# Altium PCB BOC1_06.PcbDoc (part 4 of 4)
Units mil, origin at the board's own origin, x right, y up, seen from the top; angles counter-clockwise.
Board outline 7900 x 6500 mil, 2 copper layers (Top Layer, Bottom Layer); 312 components, 413 nets, 1710 pads, 368 vias.
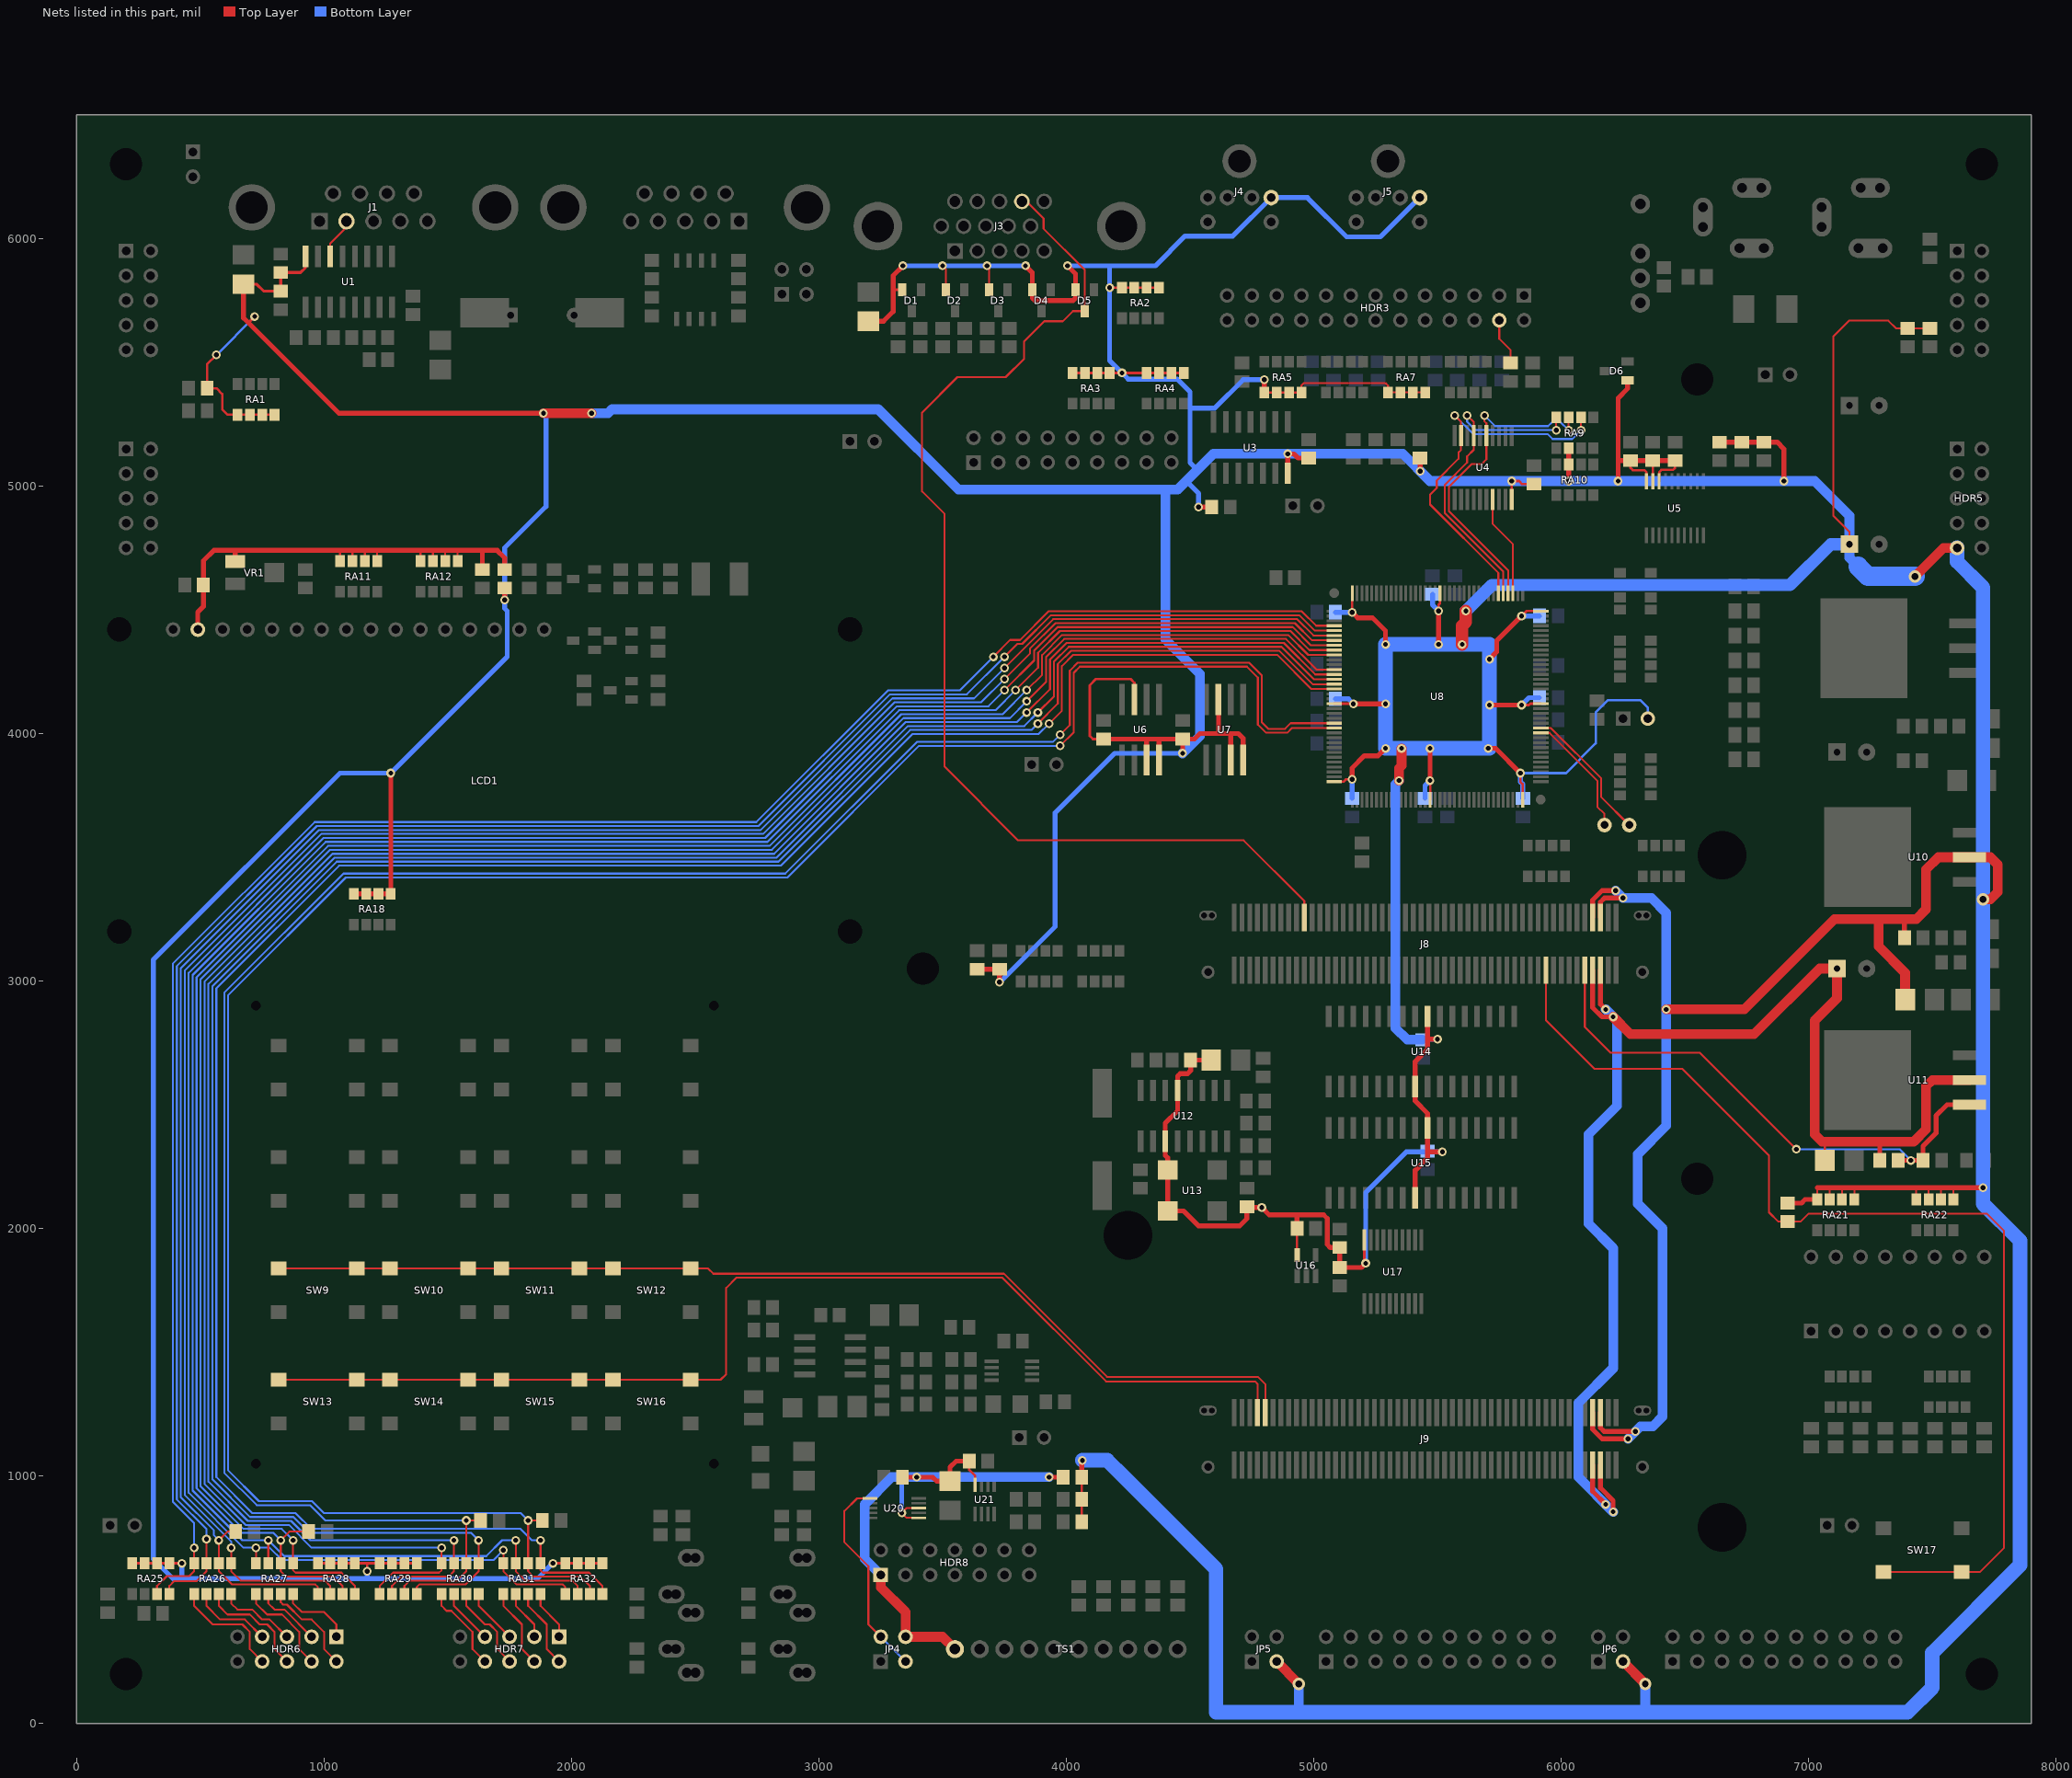
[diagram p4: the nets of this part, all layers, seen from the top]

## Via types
v1: diameter 35.43, hole 19.68, Top Layer to Bottom Layer, 194 vias
v2: diameter 35.43, hole 19.68, Top Layer to Bottom Layer, tented both sides, 169 vias
v3: diameter 50, hole 27.56, Top Layer to Bottom Layer, 5 vias

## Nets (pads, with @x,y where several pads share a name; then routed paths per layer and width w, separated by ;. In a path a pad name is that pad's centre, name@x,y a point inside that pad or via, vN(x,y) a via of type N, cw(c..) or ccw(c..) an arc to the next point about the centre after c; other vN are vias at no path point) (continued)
SWR2: J9.10 SW9.1 SW9.2 SW10.1 SW10.2 SW11.1 SW11.2 SW12.1 SW12.2 | length 4295.4
  Top Layer w7.87: SW9.1@817.13,1838.58 SW12.2@2482.48,1838.58 2551.67,1838.58 2573.25,1817 3747.81,1817 4164.56,1400.25 4774.75,1400.25 4804.33,1370.67 J9.10@4804.33,1256.3
SWR3: J9.8 SW13.1 SW13.2 SW14.1 SW14.2 SW15.1 SW15.2 SW16.1 SW16.2 | length 4624.5
  Top Layer w7.87: SW13.1@817.13,1388.58 2602.58,1388.58 2625.25,1411.25 2625.25,1760 2666.5,1801.25 3741.29,1801.25 4160.79,1381.75 4763.25,1381.75 4772.83,1372.17 J9.8@4772.83,1256.3
TCK: RA9.6 U4.9 U8.78 | length 1510
  Top Layer w7.87: v2(5570,5285) 5595,5260 5595,5145 5585,5135 5585,5110 5497,5022 5497,4992 5470,4965 5470,4925 5746.06,4648.94 U8.78@5746.06,4567.32 ; v2(6080,5225) RA9.6@6080,5277
  Bottom Layer w7.87: v2(5570,5285) 5645,5210 5945,5210 5965,5190 6045,5190 v2(6080,5225)
TCK_HARD: RA27.7 RA31.7 RA32.2 U8.117 | length 9306.6
  Top Layer w7.87: RA27.7@775,647 v1(775,740) ; v1(1775,740) 1775,615 1813,577 2003,577 2025,555 RA32.2@2025,523 ; v2(3795,4175) 3886,4266 3886,4326 3974,4414 4906,4414 4982.99,4337.01 U8.117@5082.68,4337.01
  Bottom Layer w7.87: v1(1775,740) 1720,740 1656,676 839,676 v1(775,740) 670,740 469,941 469,3024 1007,3562 2792,3562 3324,4094 3714,4094 v2(3795,4175)
TCK_HARD_A#: HDR6.3 RA27.2 | length 268.9
  Top Layer w7.87: RA27.2@775,523 775,485 800,460 840,460 HDR6.3@950,350
TCK_HARD_B#: HDR7.3 RA31.2 | length 204.1
  Top Layer w7.87: RA31.2@1775,523 1775,475 1850,400 HDR7.3@1850,350
TCK_SOFT_A: RA25.4 RA26.7 U8.113 | length 7992.4
  Top Layer w7.87: RA25.4@375,523 375,555 395,575 485,575 525,615 v1(525,745) ; v2(3750,4310) 3802,4362 3822,4362 3938,4478 4942,4478 5004.25,4415.75 U8.113@5082.68,4415.75
  Bottom Layer w7.87: v1(525,745) 525,785 405,905 405,3060 971,3626 2756,3626 3288,4158 3598,4158 v2(3750,4310)
TCK_SOFT_A#: HDR6.7 RA26.2 | length 324.8
  Top Layer w7.87: RA26.2@525,523 525,475 580,420 680,420 HDR6.7@750,350
TCK_SOFT_B: RA29.2 RA30.7 U8.123 | length 8783.2
  Top Layer w7.87: RA29.2@1275,523 1275,555 1313,593 1503,593 1525,615 v1(1525,740) ; v2(3885,4085) 3950,4150 3950,4290 4010,4350 4870,4350 5001.1,4218.9 U8.123@5082.68,4218.9
  Bottom Layer w7.87: v1(1525,740) 945,740 867,818 692,818 533,977 533,2988 1043,3498 2828,3498 3360,4030 3830,4030 v2(3885,4085)
TCK_SOFT_B#: HDR7.7 RA30.2 | length 224.8
  Top Layer w7.87: RA30.2@1525,523 1525,475 HDR7.7@1650,350
TDI: RA9.8 U4.7 U8.77 | length 1324.7
  Top Layer w7.87: v2(5620,5285) 5646.61,5258.39 5646.61,5146.61 5620,5120 5620,5095 5530,5005 5530,4890 5765.75,4654.25 U8.77@5765.75,4567.32 ; v2(5980,5225) RA9.8@5980,5277
  Bottom Layer w7.87: v2(5620,5285) 5620,5260 5654,5226 v2@5979,5226
TDI_HARD_A: RA27.5 RA28.4 U8.121 | length 8202.7
  Top Layer w7.87: v1(875,740) 875,619 885,609 1071,609 1125,555 RA28.4@1125,523 ; v2(3840,4130) 3918,4208 3918,4308 3992,4382 4888,4382 5011.73,4258.27 U8.121@5082.68,4258.27
  Bottom Layer w7.87: v1(875,740) 829,786 674,786 501,959 501,3006 1025,3530 2810,3530 3342,4062 3772,4062 v2(3840,4130)
TDI_HARD_A#: HDR6.1 RA27.4 | length 298.2
  Top Layer w7.87: RA27.4@875,523 875,485 910,450 1000,450 1050,400 HDR6.1@1050,350
TDI_HARD_B: RA31.5 RA32.4 U8.125 | length 9059
  Top Layer w7.87: v1(1875,740) 1875,619 1885,609 2071,609 2125,555 RA32.4@2125,523 ; v2(3930,4040) 3982,4092 3982,4272 4028,4318 4852,4318 4990.47,4179.53 U8.125@5082.68,4179.53
  Bottom Layer w7.87: v1(1875,740) 1840,740 1794,786 949,786 885,850 710,850 565,995 565,2970 1061,3466 2846,3466 3378,3998 3888,3998 v2(3930,4040)
TDI_HARD_B#: HDR7.1 RA31.4 | length 204.1
  Top Layer w7.87: RA31.4@1875,523 1875,475 1950,400 HDR7.1@1950,350
TDI_SOFT_A: RA26.5 RA28.2 U8.115 | length 8229.5
  Top Layer w7.87: v1(625,710) 625,615 663,577 1003,577 1025,555 RA28.2@1025,523 ; v2(3750,4220) 3854,4324 3854,4344 3956,4446 4924,4446 4993.62,4376.38 U8.115@5082.68,4376.38
  Bottom Layer w7.87: v1(625,710) 625,735 437,923 437,3042 989,3594 2774,3594 3306,4126 3656,4126 v2(3750,4220)
TDI_SOFT_A#: HDR6.5 RA26.4 | length 318.9
  Top Layer w7.87: RA26.4@625,523 625,485 650,460 710,460 750,420 780,420 HDR6.5@850,350
TDI_SOFT_B: RA29.4 RA30.5 U8.124 | length 8844.9
  Top Layer w7.87: RA29.4@1375,523 1375,551 1385,561 1571,561 1625,615 v1(1625,740) ; v2(3885,4040) 3966,4121 3966,4281 4019,4334 4861,4334 4995.79,4199.21 U8.124@5082.68,4199.21
  Bottom Layer w7.87: v1(1625,740) 1595,770 940,770 876,834 701,834 549,986 549,2979 1052,3482 2837,3482 3369,4014 3859,4014 v2(3885,4040)
TDI_SOFT_B#: HDR7.5 RA30.4 | length 224.8
  Top Layer w7.87: RA30.4@1625,523 1625,475 HDR7.5@1750,350
TDO: U4.17 U8.75 | length 412.6
  Top Layer w7.87: U4.17@5723.39,4946.06 5723.39,4846.61 5805.12,4764.88 U8.75@5805.12,4567.32
TDO_HARD_A: C78.1 RA27.6 RA28.3 U8.118 | length 8301.7
  Top Layer w7.87: C78.1@937.6,775 860,775 v1(825,740) 825,615 847,593 1037,593 1075,555 RA28.3@1075,523 ; v2(3840,4175) 3902,4237 3902,4317 3983,4398 4897,4398 4977.68,4317.32 U8.118@5082.68,4317.32
  Bottom Layer w7.87: v1(825,740) 795,770 665,770 485,950 485,3015 1016,3546 2801,3546 3333,4078 3743,4078 v2(3840,4175)
TDO_HARD_A#: HDR6.2 RA27.3 | length 398.4
  Top Layer w7.87: RA27.3@825,523 825,490 835,480 850,480 910,420 950,420 1000,370 1000,300 HDR6.2@1050,250
TDO_HARD_B: C80.1 RA31.6 RA32.3 U8.133 | length 9175.8
  Top Layer w7.87: C80.1@1882.6,820 v1(1825,820) 1825,615 1847,593 2037,593 2075,555 RA32.3@2075,523 ; v2(3975,3950) 4030,4005 4030,4245 4055,4270 4730,4270 4774,4226 4774,4036 4807,4003 4893,4003 4912.05,4022.05 U8.133@5082.68,4022.05
  Bottom Layer w7.87: v1(1825,820) 1795,850 1000,850 952,898 737,898 613,1022 613,2943 1088,3418 2873,3418 3405,3950 v2(3975,3950)
TDO_HARD_B#: HDR7.2 RA31.3 | length 324.8
  Top Layer w7.87: RA31.3@1825,523 1825,475 1900,400 1900,300 HDR7.2@1950,250
TDO_SOFT_A: C77.1 RA26.6 RA28.1 U8.114 | length 8309.8
  Top Layer w7.87: C77.1@642.6,775 610,775 v1(575,740) 575,615 629,561 965,561 975,551 RA28.1@975,523 ; v2(3750,4265) 3947,4462 4933,4462 4998.94,4396.06 U8.114@5082.68,4396.06
  Bottom Layer w7.87: v1(575,740) 555,760 555,780 421,914 421,3051 980,3610 2765,3610 3297,4142 3627,4142 v2(3750,4265)
TDO_SOFT_A#: HDR6.6 RA26.3 | length 457.2
  Top Layer w7.87: RA26.3@575,523 575,475 610,440 700,440 740,400 770,400 800,370 800,300 HDR6.6@850,250
TDO_SOFT_B: C79.1 RA29.3 RA30.6 U8.132 | length 8964.8
  Top Layer w7.87: RA29.3@1325,523 1325,555 1347,577 1537,577 1575,615 v1(1575,820) C79.1@1632.6,820 ; v2(3975,3995) 4014,4034 4014,4254 4046,4286 4739,4286 4790,4235 4790,4045 4816,4019 4884,4019 4906.73,4041.73 U8.132@5082.68,4041.73
  Bottom Layer w7.87: v1(1575,820) 1005,820 943,882 728,882 597,1013 597,2952 1079,3434 2864,3434 3396,3966 3946,3966 v2(3975,3995)
TDO_SOFT_B#: HDR7.6 RA30.3 | length 357.2
  Top Layer w7.87: RA30.3@1575,523 1575,475 1650,400 1670,400 1700,370 1700,300 HDR7.6@1750,250
TEST: J8.81 R55.2 SW17.1 SW17.2 | length 4376.4
  Top Layer w7.87: J8.81@5938.19,3043.7 5938.19,2841.81 6135,2645 6490,2645 6840,2295 6840,2065 6877.4,2027.6 6967.6,2027.6 7000,2060 7720,2060 7790,1990 7790,710 7691.42,611.42 SW17.2@7302.52,611.42
TMS: RA9.7 U4.5 U8.76 | length 1338.2
  Top Layer w7.87: v2(5690,5285) 5690,5261 5697.8,5253.2 5697.8,5107.8 5679,5089 5639,5089 5546,4996 5546,4899 5785.43,4659.57 U8.76@5785.43,4567.32 ; v2(6030,5225) RA9.7@6030,5277
  Bottom Layer w7.87: v2(5690,5285) 5733,5242 5947,5242 5965,5260 5995,5260 v2(6030,5225)
TMS_HARD: RA27.8 RA31.8 RA32.1 U8.116 | length 9216.9
  Top Layer w7.87: RA27.8@725,647 v1(725,710) ; v1(1725,700) 1725,615 1779,561 1965,561 1975,551 RA32.1@1975,523 ; v2(3750,4175) 3870,4295 3870,4335 3965,4430 4915,4430 4988.31,4356.69 U8.116@5082.68,4356.69
  Bottom Layer w7.87: v1(1725,700) 1685,660 830,660 780,710 675,710 453,932 453,3033 998,3578 2783,3578 3315,4110 3685,4110 v2(3750,4175)
TMS_HARD_A#: HDR6.4 RA27.1 | length 401.3
  Top Layer w7.87: RA27.1@725,523 725,485 770,440 830,440 900,370 900,300 HDR6.4@950,250
TMS_HARD_B#: HDR7.4 RA31.1 | length 324.8
  Top Layer w7.87: RA31.1@1725,523 1725,475 1800,400 1800,300 HDR7.4@1850,250
TMS_SOFT_A: RA25.3 RA26.8 U8.112 | length 8004.7
  Top Layer w7.87: RA25.3@325,523 325,555 365,595 455,595 475,615 v1(475,710) ; v2(3705,4310) 3773,4378 3813,4378 3929,4494 4951,4494 5009.57,4435.43 U8.112@5082.68,4435.43
  Bottom Layer w7.87: v1(475,710) 475,810 389,896 389,3069 962,3642 2747,3642 3279,4174 3569,4174 v2(3705,4310)
TMS_SOFT_A#: HDR6.8 RA26.1 | length 457.2
  Top Layer w7.87: RA26.1@475,523 475,475 550,400 670,400 700,370 700,300 HDR6.8@750,250
TMS_SOFT_B: RA29.1 RA30.8 U8.122 | length 8749.2
  Top Layer w7.87: RA29.1@1225,523 1225,555 1279,609 1465,609 1475,619 v1(1475,710) ; v2(3840,4085) 3934,4179 3934,4299 4001,4366 4879,4366 5006.42,4238.58 U8.122@5082.68,4238.58
  Bottom Layer w7.87: v1(1475,710) 950,710 858,802 683,802 517,968 517,2997 1034,3514 2819,3514 3351,4046 3801,4046 v2(3840,4085)
TMS_SOFT_B#: HDR7.8 RA30.1 | length 357.2
  Top Layer w7.87: RA30.1@1475,523 1475,475 1495,455 1515,455 1600,370 1600,300 HDR7.8@1650,250
TP_U8-47: pad.TP@6175,3630 U8.47 | length 499.8
  Top Layer w7.87: U8.47@5917.32,4002.36 5952.64,4002.36 6146,3809 6146,3704 6175,3675 pad.TP@6175,3630
TP_U8-48: pad.TP@6275,3630 U8.48 | length 564
  Top Layer w7.87: U8.48@5917.32,4022.05 5957.95,4022.05 6162,3818 6162,3743 pad.TP@6275,3630
TX: J1.2 U1.14 | length 170
  Top Layer w7.87: U1.14@1025,5927.36 1025,5980 1090.94,6045.94 J1.2@1090.94,6070.08
VCC: C1.1 C2.1 C3.1 C5.1 C10.1 C11.1 C12.2 C13.2 C14.2 C16.1 C19.2 C20.1 C25.1 C29.1 C30.1 C32.1 C33.1 C34.1 C59.1 C60.1 C61.1 C64.1 C65.1 C70.1 C72.1 C73.1 C74.1 C75.1 D1.2 D2.2 D3.2 D4.2 D5.2 D6.1 HDR5.9 J4.4 J5.4 J8.94 J8.96 J9.94 J9.96 JP3.2 JP5.3 JP6.3 R7.1 R20.1 R21.1 R24.2 R25.1 R26.1 R27.1 R28.2 R31.1 R45.2 R46.2 R47.1 R55.1 R59.1 R75.2 R77.1 R79.1 RA1.1 RA1.2 RA1.3 RA1.4 RA2.5 RA2.6 RA2.7 RA2.8 RA3.5 RA3.6 RA3.7 RA3.8 RA4.5 RA4.6 RA4.7 RA4.8 RA5.1 RA5.2 RA5.3 RA5.4 RA7.1 RA7.2 RA7.3 RA7.4 RA9.2 RA10.7 RA18.5 RA18.6 RA18.7 RA18.8 RA21.5 RA21.6 RA21.7 RA21.8 RA22.5 RA22.6 RA22.7 RA22.8 RA25.5 RA25.6 RA25.7 RA25.8 RA28.5 RA28.6 RA28.7 RA28.8 RA29.5 RA29.6 RA29.7 RA29.8 RA32.5 RA32.6 RA32.7 RA32.8 U1.16 U3.14 U4.20 U5.18 U5.19 U5.20 U6.3 U6.7 U6.8 U7.3 U7.7 U7.8 U8.17 U8.36 U8.53 U8.72 U8.90 U8.108 U8.128 U8.144 U10.2 U12.3 U12.13 U13.1 U13.4 U14.8 U14.24 U15.8 U15.24 U16.5 U17.20 | length 59998
  Top Layer w7.87: v2(3500,5890) 3512.6,5877.4 D2.2@3512.6,5793.31 ; v2(3680,5890) 3687.6,5882.4 D3.2@3687.6,5793.31 ; RA5.4@4950,5378 4950,5406 4960,5416 5290,5416 5300,5406 RA7.1@5300,5378 RA7.4@5450,5378 ; RA21.8@7035,2117 7035,2165 ; RA21.7@7085,2117 7085,2165 ; RA21.6@7135,2117 7135,2165 ; C16.1@7165,4765 7165,4815 7100,4880 7100,5605 7163,5668 7322,5668 7352.6,5637.4 R21.1@7490,5637.4 ; RA21.5@7185,2117 7185,2165 ; RA22.8@7435,2117 7435,2165 ; RA22.7@7485,2117 7485,2165 ; RA22.6@7535,2117 7535,2165 ; RA22.5@7585,2117 7585,2165
  Top Layer w9.84: RA25.8@225,647 v1(425,647) ; v2(565,5530) 527.4,5492.4 R7.1@527.4,5395 565,5395 589,5371 589,5310 611,5288 RA1.1@650,5288 RA1.2@700,5288 RA1.3@750,5288 RA1.4@800,5288 ; 695,5660 v2(720,5685) ; RA28.8@975,647 RA29.5@1375,647 ; v1(1175,615) 1175,647 ; v1(1925,647) RA32.5@2125,647 ; 3300,5793.31 D1.2@3337.6,5793.31 ; RA3.8@4025,5457 RA3.7@4075,5457 RA3.6@4125,5457 RA3.5@4175,5457 RA4.8@4325,5457 RA4.7@4375,5457 RA4.6@4425,5457 RA4.5@4475,5457 ; R79.1@4062.4,815 R75.2@4062.4,995 ; C19.2@4150,3977.6 4107.4,3977.6 4095,3990 4095,4195 4120,4220 4260,4220 4275,4205 U6.3@4275,4137.05 ; v2(4175,5802) RA2.5@4375,5802 ; RA5.1@4800,5378 RA5.4@4950,5378 ; U16.5@4932.6,1892.32 C33.1@4932.6,2000 ; U8.144@5082.68,3805.51 5120.51,3805.51 ; U8.128@5082.68,4120.47 v1@5159.53,4120.47 ; 5121.51,3805.51 5131,3815 v1(5155,3815) ; v1@5155.51,4490 U8.108@5155.51,4567.32 ; U8.17@5470.47,3732.68 v1@5470.47,3810 ; v1(5505,4495) 5505,4520 5509.84,4524.84 U8.90@5509.84,4567.32 ; U4.20@5800,4946.22 v2(5800,5020) 5830,5020 5842.4,5007.6 C11.1@5890,5007.6 ; v1(5835,3840) 5835,3805 5844.49,3795.51 U8.36@5844.49,3732.68 ; v1(5840,4115) 5870,4115 5875.47,4120.47 U8.53@5917.32,4120.47 ; v1(5840,4475) 5859.49,4494.49 U8.72@5917.32,4494.49 ; C12.2@6280,5102.6 6280,5073 6289,5064 6336,5064 6344.84,5055.16 U5.20@6344.84,5019.25 ; U5.19@6370.43,5019.25 C13.2@6370.43,5091.85 ; U5.18@6396.02,5019.25 6396.02,5056.02 6405,5065 6452,5065 6460,5073 C14.2@6460,5102.6
  Top Layer w11.81: C1.1@675,5815.95 727.06,5815.94 755.6,5787.4 C3.1@825,5787.4 C2.1@825,5862.6 905.4,5862.6 925,5882.19 U1.16@925,5927.36 ; U17.20@5204.84,1953.94 5204.84,1864.16 v2(5210,1859)
  Top Layer w19.68: C1.1@675,5815.95 675,5679 1060,5294 v2(1887,5294) ; RA18.8@1120,3352 RA18.5@1270,3352 v2(1270,3840) ; v2(1730,4540) R31.1@1730,4587.6 ; C5.1@3200,5665.95 3260.95,5665.95 3300,5705 3300,5850 v2(3340,5890) ; R45.2@3640,3047.6 R46.2@3730,3047.6 v1(3730,2995) ; v2(3835,5890) 3862.6,5862.4 D4.2@3862.6,5793.31 3862.6,5760.4 3873,5750 4028,5750 4037.6,5759.6 D5.2@4037.6,5793.31 4037.6,5857.4 v2(4005,5890) ; R75.2@4062.4,995 4062.4,1060.39 v2(4065,1062.99) ; C19.2@4150,3977.6 4517.6,3977.6 4540,4000 4695,4000 4715,3980 U7.8@4715,3892.95 ; U6.7@4325,3892.95 4325,3977.6 ; U6.8@4375,3892.95 4375,3977.6 ; v2(4470,3920) C20.1@4470,3977.6 ; v2(4535,4915) R28.2@4587.6,4915 ; C30.1@4585.95,2680 C29.1@4502.4,2680 4502.4,2637.4 4490,2625 4460,2625 4450,2615 4450,2475 4400,2425 4400,2295 4410,2285 U13.1@4410,2070.75 4474.25,2070.75 4535,2010 4700,2010 4730,2040 4730,2085 v2(4790,2085) 4820,2055 5040,2055 5055,2040 5055,1935 5067.4,1922.6 R59.1@5105,1922.6 C34.1@5105,1842.4 5193.4,1842.4 v2(5210,1859) ; 4615,4000 U7.3@4615,4137.05 ; U7.7@4665,3892.95 4665,4000 ; RA5.1@4800,5378 v1(4800,5430) ; U3.14@4895,5051.65 v2(4895,5130) 4920,5130 4937.4,5112.6 C10.1@4980,5112.6 ; C33.1@4932.6,2000 4932.6,2055 ; v1(5155,3815) 5155,3860 5205,3910 5260,3910 v1(5290,3940) ; v1(5155,4490) 5178,4467 5238,4467 5290,4415 v1(5290,4360) ; v1(5160,4120) v1(5290,4120) ; U15.8@5410,2123.27 5410,2235 5460,2285 5460,2465 5410,2515 5410,2675 5460,2725 U14.24@5460,2856.73 ; v1(5430,5060) R24.2@5430,5112.6 ; 5460,2310 v2(5520,2310) ; 5460,2765 v2(5500,2765) ; v1(5470,3810) v1(5470,3940) ; v1(5505,4360) v1(5505,4495) ; v1(5705,3940) 5735,3940 v1(5835,3840) ; v1(5710,4115) v1(5840,4115) ; v1(5710,4300) 5740,4330 5740,4375 v1(5840,4475) ; v1(6030,5020) RA9.2@6030,5153 ; J9.94@6127.17,1256.3 6127.17,1187.83 6165,1150 v1(6270,1150) ; J8.94@6127.17,3256.3 6127.17,3327.17 6165,3365 v1(6220,3365) ; J9.96@6158.66,1256.3 6158.66,1194.34 6173,1180 v1(6300,1180) ; J8.96@6158.66,3256.3 6158.66,3318.66 6175,3335 v1(6250,3335) ; v1(6230,5020) 6230,5355 6268.31,5393.31 D6.1@6268.31,5427.6 ; 6230,5102.6 C14.2@6460,5102.6 ; R25.1@6640,5177.4 6872.6,5177.4 6900,5150 v1(6900,5020) ; R55.1@6915,2102.4 6971.11,2102.4 6985.71,2117 RA21.8@7035,2117 ; 7035,2165 v2(7705,2165) ; R47.1@7387.6,3175 7387.6,3250
  Top Layer w39.37: v2(1887,5294) v2(2081,5294) ; JP5.3@4850,250 v3(4940,160) ; v1(5345,3810) 5345,3860 5355,3870 v1(5355,3940) ; JP6.3@6250,250 v3(6340,160) ; v2(6425,2885) 6740,2885 7105,3250 7435,3250 7475,3290 7475,3450 7525,3500 7735,3500 7765,3470 7765,3360 7735,3330 v3(7705,3330) ; 7283,3250 7283,3140 7390,3033 C25.1@7390,2925.95 ; v3(7430,4635) 7545,4750 HDR5.9@7600,4750
  Top Layer w50: v1(5600,4360) 5600,4435 5615,4450 v1(5615,4495)
  Bottom Layer w9.84: v2(565,5530) v2(720,5685) ; v1(5835,3840) 6020,3840 6140,3960 6140,4085 6190,4135 6320,4135 6350,4105 JP3.2@6350,4060
  Bottom Layer w19.68: 425,585 v1(425,647) ; 1175,585 v1(1175,615) ; v2(1887,5294) 1897.04,5283.96 1897.04,4917.04 1730,4750 1730,4505 1740,4495 1740,4310 v2(1270,3840) 1065,3840 310,3085 310,665 390,585 1863,585 v1(1925,647) ; v2(3340,5890) v2(3835,5890) ; v1(3730,2995) 3955,3220 3955,3680 4195,3920 v2(4470,3920) ; v2(4005,5890) 4360,5890 4480,6010 4672.6,6010 J4.4@4827.95,6165.35 4974.65,6165.35 5133,6007 5269.6,6007 J5.4@5427.95,6165.35 ; 4175,5890 4175,5507 4250,5432 4448,5432 4500,5380 4500,5095 4530,5065 ; 4485,5020 4535,4970 v2(4535,4915) ; 4500,5315 4600,5315 4715,5430 v1(4800,5430) ; C65.1@5087.4,4140 5140,4140 v1(5160,4120) ; C61.1@5087.4,4490 v1(5155,4490) ; C73.1@5155,3737.4 v1(5155,3815) ; v2(5210,1859) 5210,2145 5375,2310 v2(5520,2310) v2@5521.02,2311.02 ; C74.1@5440,2765 v2(5500,2765) ; C72.1@5450,3737.4 5450,3790 v1(5470,3810) ; C59.1@5480,4562.6 5480,4520 v1(5505,4495) ; v1(5835,3840) 5835,3805 5845,3795 C70.1@5845,3737.4 ; v1(5840,4115) 5870,4145 C64.1@5912.6,4145 ; v1(5840,4475) C60.1@5912.6,4475
  Bottom Layer w39.37: v2(2081,5294) 2148,5294 2164,5310 3240,5310 3565,4985 4450,4985 4595,5130 5360,5130 5470,5020 7025,5020 7165,4880 C16.1@7165,4765 7165,4710 7200,4675 ; 4400,4985 4400,4380 4540,4240 4540,3990 v2(4470,3920) ; 4940,45 v3(4940,160) ; v1(5345,3810) 5330,3795 5330,2810 5377.6,2762.4 C74.1@5440,2762.4 ; v1(6220,3365) v1(6250,3335) 6365,3335 6425,3275 6425,2415 6310,2300 6310,2100 6410,2000 6410,1240 6370,1200 6320,1200 v1(6270,1150) ; 6340,45 v3(6340,160)
  Bottom Layer w50: v1(5615,4495) 5720,4600 6925,4600 7090,4765 C16.1@7165,4765
  Bottom Layer w59.05: 4605,623.42 4605,45 7400,45 7500,145 7500,285 7855,640 7855,1950
  Bottom Layer w59.06: v2(4065,1062.99) 4165.43,1062.99 4233.42,995 4605,623.42 ; v1(5705,3940) v1(5290,3940) v1(5290,4360) 5710,4360 v1@5710,3940 ; HDR5.9@7600,4750 7600,4695 7705,4590 7705,2100 7855,1950
  Bottom Layer w78.74: 7200,4675 7240,4635 v3(7430,4635)
  other v2: 4225,5457
VCC_LCD: C17.1 LCD1.2 R30.2 R31.2 RA11.5 RA11.6 RA11.7 RA11.8 RA12.5 RA12.6 RA12.7 RA12.8 VR1.CW | length 2048.3
  Top Layer w7.87: RA11.8@1065,4697 1065,4740 ; RA11.7@1115,4697 1115,4740 ; RA11.6@1165,4697 1165,4740 ; RA11.5@1215,4697 1215,4740 ; RA12.8@1390,4697 1390,4740 ; RA12.7@1440,4697 1440,4740 ; RA12.6@1490,4697 1490,4740 ; RA12.5@1540,4697 1540,4740
  Top Layer w19.68: LCD1.2@490,4420 490,4490 512.4,4512.4 C17.1@512.4,4600 512.4,4697.4 555,4740 641.26,4740 ; VR1.CW@641.26,4695.28 641.26,4740 ; R30.2@1640,4662.4 1640,4740 ; R31.2@1730,4662.4 1730,4710 1700,4740 1640,4740 ; 641.26,4740 1065,4740 1115,4740 1165,4740 1215,4740 1390,4740 1440,4740 1490,4740 1540,4740 1640,4740
VCC_SENSE: HDR3.15 R17.1 | length 161.2
  Top Layer w7.87: 5750,5640 5750,5595 5795,5550 R17.1@5795,5497.4
VCCA: C47.1 C48.1 C49.1 HDR8.1 JP4.4 R75.1 TS1.1 U20.1 U20.3 U21.8 | length 2419.4
  Top Layer w7.87: U20.1@3403.43,830.63 3354.37,830.63 v2(3335,850) 3355,870 U20.3@3403.43,870
  Top Layer w9.84: C49.1@3607.6,1060 3607.6,1024.4 3631.61,1000.39 U21.8@3631.61,964.06
  Top Layer w19.68: C47.1@3337.4,995 3460,995 3475.95,979.05 C48.1@3530,979.05 3530,1035 3555,1060 C49.1@3607.6,1060 ; v2(3930,995) R75.1@3987.6,995
  Top Layer w39.37: HDR8.1@3250,600 3250,550 3350,450 JP4.4@3350,350 3500,350 TS1.1@3550,300
  Bottom Layer w19.68: v2(3335,850) 3335,995
  Bottom Layer w39.37: HDR8.1@3250,600 3185,665 3185,885 3295,995 v2(3930,995)
  other v1: 3395,995
VCCINT: C24.1 C35.1 J8.93 J8.95 J9.93 J9.95 R56.1 U11.2 | length 5793
  Top Layer w9.84: C35.1@7065.95,2275 7065.95,2350
  Top Layer w19.68: J9.93@6127.17,1043.7 6127.17,937.83 v1(6180,885) ; J8.93@6127.17,3043.7 6127.17,2892.83 6165,2855 v2(6210,2855) ; J9.95@6158.66,1043.7 6158.66,951.34 6210,900 v1(6210,855) ; J8.95@6158.66,3043.7 6158.66,2906.34 v2(6180,2885) ; R56.1@7287.6,2275.1 7287.6,2337.4
  Top Layer w39.37: v2(6210,2855) 6280,2785 6780,2785 7045,3050 C24.1@7115,3050 7115,2930 7025,2840 7025,2380 7055,2350 7425,2350 7475,2400 7475,2575 7500,2600 U11.2@7650,2600
  Bottom Layer w39.37: v2(6180,2885) 6225,2840 6225,2495 6110,2380 6110,2020 6210,1920 6210,1435 6070,1295 6070,995 v1(6210,855)
VDRIVE: D5.3 J3.14 J8.20 | length 4642.8
  Top Layer w7.87: J3.14@3820.47,6150 3839,6150 3908,6081 3908,6040 4075,5873 D5.3@4075,5706.69 4026.69,5706.69 3986,5666 3911,5666 3829,5584 3829,5514 3755,5440 3560,5440 3417,5297 3417,4978 3508,4887 3508,3866 3805,3568 4717,3568 4961.81,3323.19 J8.20@4961.81,3256.3
VREF: J8.91 R56.2 R57.1 U11.1 | length 2225.6
  Top Layer w7.87: J8.91@6095.67,3043.7 6095.67,2814.33 6200,2710 6560,2710 v1(6950,2320)
  Top Layer w19.68: R56.2@7362.4,2275.1 R57.1@7462.6,2275.1 ; R57.1@7462.6,2275 7462.6,2332.6 7515,2385 7515,2455 7560,2500 U11.1@7650,2500
  Bottom Layer w7.87: v1(6950,2320) 7368,2320 v2(7413,2275)
VREF_AOUT: JP4.2 JP4.3 U20.6 | length 835.2
  Top Layer w7.87: U20.6@3206.57,909.37 3154.37,909.37 3103,858 3103,732 3200,635 3200,400 JP4.2@3250,350
  Bottom Layer w7.87: JP4.2@3250,350 JP4.3@3350,250
pads on no net: D6.2 HDR1.5 HDR1.8 HDR2.9 HDR3.1 HDR3.14 HDR3.16 HDR4.5 HDR4.8 J1.9 J2.1 J2.3 J2.5 J2.6 J2.8 J3.4 J3.9 J3.11 J3.12 J3.15 J4.2 J4.6 J5.2 J5.6 J9.76 J9.78 J9.79 J9.80 J9.81 J9.82 J9.83 J9.84 J9.85 J9.86 J9.87 J9.88 J9.89 J9.90 J9.91 J9.92 LCD1.M1 LCD1.M2 LCD1.M3 LCD1.M4 RA9.4 RA9.5 RA10.1 RA10.8 RA13.4 RA13.5 U2.5 U5.2 U5.9 U5.12 U5.13 U5.14 U5.15 U5.16 U8.FID1 U8.FID2 U9.4 U10.4 U11.4 U12.2 U12.4 U12.7 U12.10 U12.14 U12.15 U16.1

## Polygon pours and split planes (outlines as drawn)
GND on Top Layer "Top Layer-GND 6" (solid, remove dead copper, pour order 1008): 7893.01,6493.01 7894.26,6490 7894.26,10 7893.01,6.99 7890,5.74 4580,5.74 4576.99,6.99 4575.74,10 4575.74,675.74 4130,675.74 4126.99,676.99 4125.74,680 4125.74,1100.74 3775,1100.74 3771.99,1101.99 3756.99,1116.99 3755.74,1120 3755.74,1190 3756.99,1193.01 3771.99,1208.01 3775,1209.26 4150.74,1209.26 4150.74,1915 4151.99,1918.01 4155,1919.26 4940.74,1919.26 4940.74,2830.74 3745,2830.74 3741.99,2831.99 2826.99,3746.99 2825.74,3750 2825.74,4643.23 2558.23,4910.74 1985,4910.74 1981.99,4911.99 1980.74,4915 1980.74,5225 1981.99,5228.01 1985,5229.26 2275.74,5229.26 2275.74,5390 2276.99,5393.01 2280,5394.26 4590.74,5394.26 4590.74,5895 4591.99,5898.01 4595,5899.26 6185.74,5899.26 6185.74,6490 6186.99,6493.01 6190,6494.26 7890,6494.26
GND on Top Layer "Top Layer-GND 5" (solid, remove dead copper, pour order 1007): 1743.01,4803.01 1744.26,4800 1744.26,4296.77 2056.77,3984.26 2800,3984.26 2803.01,3983.01 2804.26,3980 2804.26,3736.77 3731.77,2809.26 3930,2809.26 3933.01,2808.01 3934.26,2805 3934.26,2111.77 4128.01,1918.01 4129.26,1915 4129.26,1420 4128.01,1416.99 4125,1415.74 4121.99,1416.99 3783.23,1755.74 2684.26,1755.74 2684.26,960 2683.38,957.87 2683.01,956.99 2648.01,921.99 2645,920.74 2179.26,920.74 2179.26,10 2178.01,6.99 2175,5.74 10,5.74 6.99,6.99 5.74,10 5.74,4625 6.99,4628.01 10,4629.26 328.23,4629.26 501.99,4803.01 505,4804.26 1740,4804.26
GND on Top Layer "Top Layer-GND 4" (solid, remove dead copper, pour order 1006): 2109.86,6489.86 2111.11,6486.85 2111.11,6368.15 2109.86,6365.14 2106.85,6363.89 680.85,6363.89 680.19,6363.62 491.38,6174.81 491.11,6174.15 491.11,5840.85 491.38,5840.19 875.19,5456.38 875.85,5456.11 1331.85,5456.11 1334.86,5454.86 1336.11,5451.85 1336.11,5361.77 1336.77,5361.11 1736.85,5361.11 1739.86,5359.86 1741.11,5356.85 1741.11,4833.15 1739.86,4830.14 1736.85,4828.89 490.85,4828.89 490.19,4828.62 316.71,4655.14 313.7,4653.89 13.15,4653.89 10.14,4655.14 8.89,4658.15 8.89,6486.85 10.14,6489.86 13.15,6491.11 2106.85,6491.11
GND on Top Layer "Top Layer-GND 3" (solid, remove dead copper, pour order 1005): 2109.86,6334.86 2111.11,6331.85 2111.11,6003.15 2109.86,6000.14 2106.85,5998.89 1431.77,5998.89 1431.11,5998.23 1431.11,5686.3 1429.86,5683.29 1336.38,5589.81 1336.11,5589.15 1336.11,5488.15 1334.86,5485.14 1331.85,5483.89 891.3,5483.89 888.29,5485.14 520.14,5853.29 518.89,5856.3 518.89,6158.7 520.14,6161.71 693.29,6334.86 696.3,6336.11 2106.85,6336.11
GND on Top Layer "Top Layer-GND 2" (solid, remove dead copper, pour order 1004): 2109.86,5969.86 2111.11,5966.85 2111.11,5915.85 2111.38,5915.19 2249.86,5776.71 2251.11,5773.7 2251.11,5258.15 2249.86,5255.14 2246.85,5253.89 1956.77,5253.89 1956.11,5253.23 1956.11,4886.77 1956.77,4886.11 2543.7,4886.11 2546.71,4884.86 2799.86,4631.71 2801.11,4628.7 2801.11,4013.15 2799.86,4010.14 2796.85,4008.89 2071.3,4008.89 2068.29,4010.14 1770.14,4308.29 1768.89,4311.3 1768.89,5388.23 1768.23,5388.89 1368.15,5388.89 1365.14,5390.14 1363.89,5393.15 1363.89,5573.7 1365.14,5576.71 1458.62,5670.19 1458.89,5670.85 1458.89,5966.85 1460.14,5969.86 1463.15,5971.11 2106.85,5971.11
AGND on Top Layer "Top Layer-AGND 1" (solid, remove dead copper, pour order 1003): 3773.01,1733.01 4128.01,1378.01 4129.26,1375 4129.26,1235 4128.01,1231.99 4125,1230.74 3761.77,1230.74 3734.26,1203.23 3734.26,1170 3733.01,1166.99 3730,1165.74 3039.26,1165.74 3039.26,10 3038.01,6.99 3035,5.74 2205,5.74 2201.99,6.99 2200.74,10 2200.74,895 2201.99,898.01 2205,899.26 2658.23,899.26 2705.74,946.77 2705.74,1730 2706.99,1733.01 2710,1734.26 3770,1734.26
AGND on Top Layer "Top Layer-AGND" (solid, remove dead copper, pour order 1002): 3733.01,1143.01 3734.26,1140 3734.26,1106.77 3761.77,1079.26 4100,1079.26 4103.01,1078.01 4104.26,1075 4104.26,654.26 4550,654.26 4553.01,653.01 4554.26,650 4554.26,10 4553.01,6.99 4550,5.74 3065,5.74 3061.99,6.99 3060.74,10 3060.74,1140 3061.99,1143.01 3065,1144.26 3730,1144.26
GND on Top Layer "Top Layer-GND 1" (solid, remove dead copper, pour order 1001): 4918.01,2808.01 4919.26,2805 4919.26,1945 4918.01,1941.99 4915,1940.74 4140,1940.74 4136.99,1941.99 3956.99,2121.99 3955.74,2125 3955.74,2805 3956.99,2808.01 3960,2809.26 4915,2809.26
GND on Top Layer "Top Layer-GND" (solid, remove dead copper, pour order 1000): 6159.86,6384.86 6161.11,6381.85 6161.11,5928.15 6159.86,5925.14 6156.85,5923.89 4566.77,5923.89 4566.11,5923.23 4566.11,5423.15 4564.86,5420.14 4561.85,5418.89 2283.15,5418.89 2280.14,5420.14 2278.89,5423.15 2278.89,5789.15 2278.62,5789.81 2180.14,5888.29 2178.89,5891.3 2178.89,6133.7 2180.14,6136.71 2278.62,6235.19 2278.89,6235.85 2278.89,6353.7 2280.14,6356.71 2308.29,6384.86 2311.3,6386.11 6156.85,6386.11
GND on Bottom Layer "Bottom Layer-GND 6" (solid, remove dead copper, pour order 1017): 7893.01,6493.01 7894.26,6490 7894.26,10 7893.01,6.99 7890,5.74 4580,5.74 4576.99,6.99 4575.74,10 4575.74,675.74 4130,675.74 4126.99,676.99 4125.74,680 4125.74,1100.74 3775,1100.74 3771.99,1101.99 3756.99,1116.99 3755.74,1120 3755.74,1190 3756.99,1193.01 3771.99,1208.01 3775,1209.26 4150.74,1209.26 4150.74,1388.23 3971.99,1566.99 3970.74,1570 3970.74,2065 3971.99,2068.01 3975,2069.26 3978.01,2068.01 4126.77,1919.26 4940.74,1919.26 4940.74,2830.74 3745,2830.74 3741.99,2831.99 2826.99,3746.99 2825.74,3750 2825.74,4643.23 2558.23,4910.74 1985,4910.74 1981.99,4911.99 1980.74,4915 1980.74,5225 1981.99,5228.01 1985,5229.26 2275.74,5229.26 2275.74,5390 2276.99,5393.01 2280,5394.26 4590.74,5394.26 4590.74,5895 4591.99,5898.01 4595,5899.26 6185.74,5899.26 6185.74,6490 6186.99,6493.01 6190,6494.26 7890,6494.26
GND on Bottom Layer "Bottom Layer-GND 5" (solid, remove dead copper, pour order 1016): 1743.01,4803.01 1744.26,4800 1744.26,4296.77 2056.77,3984.26 2800,3984.26 2803.01,3983.01 2804.26,3980 2804.26,3736.77 3731.77,2809.26 3930,2809.26 3933.01,2808.01 3934.26,2805 3934.26,1615 3933.01,1611.99 3930,1610.74 3927.87,1611.62 3926.99,1611.99 3783.23,1755.74 2684.26,1755.74 2684.26,960 2683.38,957.87 2683.01,956.99 2648.01,921.99 2645,920.74 2179.26,920.74 2179.26,10 2178.01,6.99 2175,5.74 10,5.74 6.99,6.99 5.74,10 5.74,4625 6.99,4628.01 10,4629.26 328.23,4629.26 501.99,4803.01 505,4804.26 1740,4804.26
GND on Bottom Layer "Bottom Layer-GND 4" (solid, remove dead copper, pour order 1015): 2109.86,6489.86 2111.11,6486.85 2111.11,6368.15 2109.86,6365.14 2106.85,6363.89 680.85,6363.89 680.19,6363.62 491.38,6174.81 491.11,6174.15 491.11,5840.85 491.38,5840.19 875.19,5456.38 875.85,5456.11 1331.85,5456.11 1334.86,5454.86 1336.11,5451.85 1336.11,5361.77 1336.77,5361.11 1736.85,5361.11 1739.86,5359.86 1741.11,5356.85 1741.11,4833.15 1739.86,4830.14 1736.85,4828.89 490.85,4828.89 490.19,4828.62 316.71,4655.14 313.7,4653.89 13.15,4653.89 10.14,4655.14 8.89,4658.15 8.89,6486.85 10.14,6489.86 13.15,6491.11 2106.85,6491.11
GND on Bottom Layer "Bottom Layer-GND 3" (solid, remove dead copper, pour order 1014): 2109.86,6334.86 2111.11,6331.85 2111.11,6003.15 2109.86,6000.14 2106.85,5998.89 1431.77,5998.89 1431.11,5998.23 1431.11,5686.3 1429.86,5683.29 1336.38,5589.81 1336.11,5589.15 1336.11,5488.15 1334.86,5485.14 1331.85,5483.89 891.3,5483.89 888.29,5485.14 520.14,5853.29 518.89,5856.3 518.89,6158.7 520.14,6161.71 693.29,6334.86 696.3,6336.11 2106.85,6336.11
GND on Bottom Layer "Bottom Layer-GND 2" (solid, remove dead copper, pour order 1013): 2109.86,5969.86 2111.11,5966.85 2111.11,5915.85 2111.38,5915.19 2249.86,5776.71 2251.11,5773.7 2251.11,5258.15 2249.86,5255.14 2246.85,5253.89 1956.77,5253.89 1956.11,5253.23 1956.11,4886.77 1956.77,4886.11 2543.7,4886.11 2546.71,4884.86 2799.86,4631.71 2801.11,4628.7 2801.11,4013.15 2799.86,4010.14 2796.85,4008.89 2071.3,4008.89 2068.29,4010.14 1770.14,4308.29 1768.89,4311.3 1768.89,5388.23 1768.23,5388.89 1368.15,5388.89 1365.14,5390.14 1363.89,5393.15 1363.89,5573.7 1365.14,5576.71 1458.62,5670.19 1458.89,5670.85 1458.89,5966.85 1460.14,5969.86 1463.15,5971.11 2106.85,5971.11
AGND on Bottom Layer "Bottom Layer-AGND 1" (solid, remove dead copper, pour order 1012): 3773.01,1733.01 4128.01,1378.01 4129.26,1375 4129.26,1235 4128.01,1231.99 4125,1230.74 3761.77,1230.74 3734.26,1203.23 3734.26,1170 3733.01,1166.99 3730,1165.74 3039.26,1165.74 3039.26,10 3038.01,6.99 3035,5.74 2205,5.74 2201.99,6.99 2200.74,10 2200.74,895 2201.99,898.01 2205,899.26 2658.23,899.26 2705.74,946.77 2705.74,1730 2706.99,1733.01 2710,1734.26 3770,1734.26
AGND on Bottom Layer "Bottom Layer-AGND" (solid, remove dead copper, pour order 1011): 3733.01,1143.01 3734.26,1140 3734.26,1106.77 3761.77,1079.26 4100,1079.26 4103.01,1078.01 4104.26,1075 4104.26,654.26 4550,654.26 4553.01,653.01 4554.26,650 4554.26,10 4553.01,6.99 4550,5.74 3065,5.74 3061.99,6.99 3060.74,10 3060.74,1140 3061.99,1143.01 3065,1144.26 3730,1144.26
GND on Bottom Layer "Bottom Layer-GND 1" (solid, remove dead copper, pour order 1010): 4918.01,2808.01 4919.26,2805 4919.26,1945 4918.01,1941.99 4915,1940.74 4140,1940.74 4136.99,1941.99 3956.99,2121.99 3955.74,2125 3955.74,2805 3956.99,2808.01 3960,2809.26 4915,2809.26
GND on Bottom Layer "Bottom Layer-GND" (solid, remove dead copper, pour order 1009): 6159.86,6384.86 6161.11,6381.85 6161.11,5928.15 6159.86,5925.14 6156.85,5923.89 4566.77,5923.89 4566.11,5923.23 4566.11,5423.15 4564.86,5420.14 4561.85,5418.89 2283.15,5418.89 2280.14,5420.14 2278.89,5423.15 2278.89,5789.15 2278.62,5789.81 2180.14,5888.29 2178.89,5891.3 2178.89,6133.7 2180.14,6136.71 2278.62,6235.19 2278.89,6235.85 2278.89,6353.7 2280.14,6356.71 2308.29,6384.86 2311.3,6386.11 6156.85,6386.11

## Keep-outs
Keep-Out Layer:
  circle w7.87: c200,200 r157.48
  circle w7.87: c725,2900 r63.51
  circle w7.87: c2575,2900 r63.51
  circle w7.87: c2575,1050 r63.51
  circle w7.87: c725,1050 r63.51
  circle w7.87: c200,6300 r157.48
  circle w7.87: c7700,6300 r157.48
  circle w7.87: c7700,200 r157.48
  circle w7.87: c3420,3050 r157.48
  circle w7.87: c6550,2200 r157.48
  circle w7.87: c6550,5430 r157.48
  lines w7.87: 0,0 7900,0 7900,6500 0,6500 0,0

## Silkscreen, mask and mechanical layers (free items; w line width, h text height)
Top Overlay:
  drawing of 206 lines, arcs and shapes, not listed
  text "GND" at 390,6415 h59.06
  text "NanoTalk Master" at 48.11,6030.69 h59.06 r270
  text "NANOTALK" at 5660,5995 h59.06
  text "PS2 KB" at 4600,5920 h59.06
  text "MOUSE" at 5210,5920 h59.06
  text "PARALLEL" at 5660,5915 h59.06
  text "5 VDC" at 6890,5820 h59.06
  text "OFF/ON" at 6215,5600 h78.74
  text "1-2 CAN SPEED" at 2551,5553 h47.24
  text "CAN" at 2230,5470 h78.74
  text "3-4 CAN LOAD" at 2551,5453 h47.24
  text "NanoTalk Slave" at 7858,5428 h59.06 r90
  text "VGA" at 3267,5410 h78.74 r90
  text "RS232" at 1070,5330 h78.74
  text "GND" at 6805,5325 h59.06
  text "Master I/O" at 44.1,5154.44 h59.06 r270
  text "NB1" at 510,5125 h62.99
  text "REV 1.06" at 790,5125 h62.99
  text "GND" at 3106.81,5053.19 h59.06
  text "AUTO LOAD FPGA" at 3605,5005 h47.24 r270
  text "CLOCK0" at 3700,5005 h47.24 r270
  text "CLOCK1" at 3800,5005 h47.24 r270
  text "CLOCK2" at 3900,5005 h47.24 r270
  text "USER A - BYPASS SOFT" at 4000,5005 h37.4 r270
  text "USER B - BYPASS SOFT" at 4100,5005 h37.4 r270
  text "TEST 0" at 4200,5005 h47.24 r270
  text "TEST 1" at 4300,5005 h47.24 r270
  text "SYSTEM JTAG" at 4400,5005 h47.24 r270
  text "GND" at 4885,4795 h59.06
  text "CONTRAST" at 575,4770 h39.37
  text "Slave I/O" at 7855,4735 h59.06 r90
  text "SL1" at 6477.6,4565 h59.06
  text "SL2" at 6477.6,4465 h59.06
  text "SL3" at 6477.6,4365 h59.06
  text "SL4" at 6477.6,4265 h59.05
  text "SL5" at 6477.6,4165 h59.05
  text "SL6" at 6477.6,4065 h59.05
  text "SL7" at 6477.6,3965 h59.05
  text "SL8" at 6477.6,3865 h59.05
  text "GND" at 3840,3750 h59.05
  text "P47" at 6165,3495 h31.5 r90
  text "P48" at 6265,3495 h31.5 r90
  text "CLOCK0" at 3100,2760 h43.31
  text "CLOCK1" at 3410,2760 h43.31
  text "CLOCK2" at 3700,2760 h43.31
  text "10MHz" at 2785,2660 h47.24
  text "20MHz" at 2785,2560 h47.24
  text "30MHz" at 2785,2460 h47.24
  text "abc" at 1420,2445 h59.06
  text "def" at 1880,2445 h59.06
  text "C" at 2201,2406 h98.43
  text "1" at 850,2405 h98.43
  text "2" at 1295,2405 h98.43
  text "3" at 1745,2405 h98.43
  text "40MHz" at 2785,2360 h47.24
  text "50MHz" at 2785,2260 h47.24
  text "60MHz" at 2785,2160 h47.24
  text "RAM - 256K x 8" at 5944,2139 h59.06 r90
  text "75MHz" at 2785,2060 h47.24
  text "ghi" at 995,1995 h59.06
  text "jkl" at 1475,1995 h59.06
  text "mno" at 1845,1995 h59.06
  text "100MHz" at 2785,1960 h47.24
  text "4" at 830,1955 h98.43
  text "6" at 1750,1955 h98.43
  text "5" at 1300,1950 h98.43
  text "D" at 2210,1950 h98.43
  text "STARTUP FREQUENCY" at 2865,1817 h59.05
  text "pqrs" at 950,1545 h59.06
  text "tuv" at 1440,1545 h59.06
  text "wxyz" at 1830,1545 h59.06
  text "7" at 850,1500 h98.43
  text "8" at 1295,1500 h98.43
  text "9" at 1745,1500 h98.43
  text "E" at 2205,1500 h98.43
  text "*+" at 955,1095 h59.06
  text "#^" at 1845,1095 h59.06
  text "A" at 855,1050 h98.43
  text "0" at 1295,1050 h98.43
  text "B" at 1750,1050 h98.43
  text "F" at 2210,1050 h98.43
  text "GND" at 3785,1030 h59.06
  text "AUDIO" at 2530,835 h59.06
  text "GND" at 305,790 h59.06
  text "IN" at 2510,740 h59.06
  text "OUT" at 2640,740 h59.06
  text "GND" at 7045,675 h59.06
  text "TEST/RESET" at 7175,500 h59.06
  text "I2C/ DAC/ADC" at 3220,460 h59.06
  text "0" at 3640,115 h39.37
  text "1" at 3745,115 h39.37
  text "2" at 3830,115 h39.37
  text "3" at 3935,115 h39.37
  text "0" at 4030,115 h39.37
  text "1" at 4125,115 h39.37
  text "2" at 4230,115 h39.37
  text "3" at 4340,115 h39.37
  text "VCC" at 3410,110 h39.37
  text "GND" at 4485,110 h39.37
  text "REF" at 4315,70 h35.43
  text "5V" at 4775,70 h47.24 r90
  text "5V" at 6175,70 h47.24 r90
  text "3V3" at 3375,55 h47.24 r90
  text "3V3" at 4875,55 h47.24 r90
  text "3V3" at 6275,55 h47.24 r90
  text "AIN3" at 3275,45 h47.24 r90
  text "USER BOARD A" at 540,35 h59.05
  text "USER BOARD B" at 1440,35 h59.05
  text "USER HEADER A" at 5165,30 h59.06
  text "USER HEADER B" at 6565,30 h59.06
  text "ANALOG OUT" at 3610,15 h39.37
  text "ANALOG IN" at 4055,15 h39.37
Boundary:
  the board outline again, w7.87
  text "PCB boundary coincides with centre-line of tracks" at 0,-472.44 h29.53
Gerber ID:
  text ".Layer_Name" at 0,-236.22 h29.53
Printout ID:
  text ".Printout_Name" at 0,-393.7 h29.53
Satellite PCB Boundary:
  lines w9.84: 4091.42,3665.75 4091.42,634.25 6807.95,634.25 6807.95,3665.75 ccw(c5449.68,-2113.8) 4091.44,3665.75
Mechanical 7:
  lines w6.3: 3930,1570 4125,1375 ; 4125,1375 4125,1235 3760,1235 3730,1205 3730,1170 3035,1170 3035,10 2205,10 2205,895 2660,895 2710,945 2710,1730 3770,1730 4125,1375 ; 10,10 10,4625 330,4625 505,4800 1740,4800 1740,4295 2055,3980 2800,3980 2800,3735 3730,2805 3930,2805 3930,2110 4125,1915 4125,1420 3785,1760 2680,1760 2680,960 2645,925 2175,925 2175,10 10,10 ; 10,4655 10,6490 2110,6490 2110,6365 680,6365 490,6175 490,5840 875,5455 1335,5455 1335,5360 1740,5360 1740,4830 490,4830 315,4655 10,4655 ; 520,5855 520,6160 695,6335 2110,6335 2110,6000 1430,6000 1430,5685 1335,5590 1335,5485 890,5485 520,5855 ; 1365,5390 1365,5575 1460,5670 1460,5970 2110,5970 2110,5915 2250,5775 2250,5255 1955,5255 1955,4885 2545,4885 2800,4630 2800,4010 2070,4010 1770,4310 1770,5390 1365,5390 ; 1985,4915 1985,5225 2280,5225 2280,5390 4595,5390 4595,5895 6190,5895 6190,6490 7890,6490 7890,10 4580,10 4580,680 4130,680 4130,1105 3775,1105 3760,1120 3760,1190 3775,1205 4155,1205 4155,1915 4780,1915 4780,1575 4580,1375 4580,1280 4610,1250 4730,1250 4945,1465 4945,4215 4780,4215 4780,2835 3745,2835 2830,3750 2830,4645 2560,4915 1985,4915 ; 2180,5890 2280,5790 2280,5420 4565,5420 4565,5925 6160,5925 6160,6385 2310,6385 2280,6355 2280,6235 2180,6135 2180,5890 ; 3065,10 4550,10 4550,650 4100,650 4100,1075 3760,1075 3730,1105 3730,1140 3065,1140 3065,10 ; 3960,2125 3960,2805 4810,2805 4810,4185 4915,4185 4915,1480 4715,1280 4625,1280 4610,1295 4610,1360 4810,1560 4810,1945 4140,1945 3960,2125
  text "GND" at 2770,6000 h100
  text "GND" at 890,5945 h100
  text "GND" at 1795,5595 h100
  text "GND" at 365,5255 h100
  text "GND" at 6240,3555 h100
  text "GND" at 1660,2470 h100
  text "GND" at 4305,2280 h100
  text "AGND" at 3160,1300 h100
  text "AGND" at 3815,360 h100
Mechanical 15:
  lines w7.87: 3110,530 3480,530 3480,490 3620,490 3620,530 3990,530 3990,770 3110,770 3110,530
Drill Drawing:
  text ".Legend" at 0,-314.96 h29.53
